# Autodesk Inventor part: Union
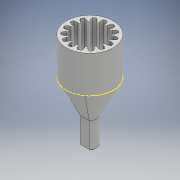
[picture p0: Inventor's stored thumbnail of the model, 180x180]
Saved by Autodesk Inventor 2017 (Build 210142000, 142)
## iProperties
Created: 2019-07
Part Number: Union
Material: Genérico
Document SubType Name: Modeling
Designer: Diego
Density: 1 g/cm^3
Appearance: Valor por defecto
Sending System: Autodesk Translation Framework v8.2.0.1029
Preprocessor: ST-DEVELOPER v18
Title: C:/Users/Diego/Downloads/9/Animalitos/Engranaje.step
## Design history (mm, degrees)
feature "Body1"
sketch "Boceto1"
  geometry: C1 r 1 at (0.304, -4.722) reference; C2 r 1 at (0.304, -4.722) reference; C3 r 7 at (0.304, -4.722); A1 r 5.95 centre (0.304, -4.722) between (1.448, 1.117) and (0.879, 1.2) reference; A2 r 5.95 centre (0.304, -4.722) between (-1.025, 1.078) and (-1.58, 0.922) reference; A3 r 5.95 centre (0.304, -4.722) between (-3.269, 0.036) and (-3.712, -0.332) reference; A4 r 5.95 centre (0.304, -4.722) between (-4.896, -1.829) and (-5.151, -2.345) reference; A5 r 5.95 centre (0.304, -4.722) between (-5.623, -4.194) and (-5.646, -4.769) reference; A6 r 5.95 centre (0.304, -4.722) between (-5.325, -6.65) and (-5.112, -7.185) reference; A7 r 5.95 centre (0.304, -4.722) between (-4.054, -8.773) and (-3.642, -9.175) reference; A8 r 5.95 centre (0.304, -4.722) between (-2.03, -10.195) and (-1.49, -10.395) reference; A9 r 5.95 centre (0.304, -4.722) between (0.398, -10.671) and (0.973, -10.634) reference; A10 r 5.95 centre (0.304, -4.722) between (2.81, -10.118) and (3.32, -9.851) reference; A11 r 5.95 centre (0.304, -4.722) between (4.788, -8.632) and (5.145, -8.181) reference; A12 r 5.95 centre (0.304, -4.722) between (5.991, -6.47) and (6.134, -5.913) reference; A13 r 5.95 centre (0.304, -4.722) between (6.211, -4.006) and (6.114, -3.439) reference; A14 r 5.95 centre (0.304, -4.722) between (5.409, -1.665) and (5.09, -1.186) reference; A15 r 5.95 centre (0.304, -4.722) between (3.724, 0.147) and (3.238, 0.454) reference; 31 further points
  constraints: 1 centre point, 1 coincident, 45 other
  dimensions: "d0" = 14 diameter of C3
extrude "Extrusión1" new body sketch "Boceto1" stored distance "d1" = 10; taper "d2" = 0 deg
sketch "Boceto2"
  geometry: C1 r 7 at (0, 0) reference; A1 r 5.95 centre (0, 0) between (3.726, 4.639) and (3.26, 4.977) reference; A2 r 5.95 centre (0, 0) between (5.291, 2.722) and (5.003, 3.221) reference; A3 r 5.95 centre (0, 0) between (5.941, 0.335) and (5.88, 0.907) reference; A4 r 5.95 centre (0, 0) between (5.563, -2.11) and (5.741, -1.563) reference; A5 r 5.95 centre (0, 0) between (4.224, -4.191) and (4.609, -3.763) reference; A6 r 5.95 centre (0, 0) between (2.154, -5.546) and (2.68, -5.312) reference; A7 r 5.95 centre (0, 0) between (-0.288, -5.943) and (0.288, -5.943) reference; A8 r 5.95 centre (0, 0) between (-2.68, -5.312) and (-2.154, -5.546) reference; A9 r 5.95 centre (0, 0) between (-4.609, -3.763) and (-4.224, -4.191) reference; A10 r 5.95 centre (0, 0) between (-5.741, -1.563) and (-5.563, -2.11) reference; A11 r 5.95 centre (0, 0) between (-5.88, 0.907) and (-5.941, 0.335) reference; A12 r 5.95 centre (0, 0) between (-5.003, 3.221) and (-5.291, 2.722) reference; A13 r 5.95 centre (0, 0) between (-3.26, 4.977) and (-3.726, 4.639) reference; A14 r 5.95 centre (0, 0) between (-0.954, 5.873) and (-1.517, 5.753) reference; A15 r 5.95 centre (0, 0) between (1.517, 5.753) and (0.954, 5.873) reference; 31 further points
  constraints: 1 horizontal alignment, 44 other
extrude "Extrusión2" cut sketch "Boceto2" distance "d3" = 1; taper "d4" = 0 deg
feature "Engrosado1" dims "d5" = 0.2, "d6" = 0.2
node "Plano de trabajo1"
sketch "Boceto3"
  geometry: L1 (-125.7, 2.5)-(-129.2, 2.5); L2 (-129.2, 2.5)-(-129.2, 3.823); L3 (-129.2, 2.5)-(-129.2, 1.177); L4 (-129.4, 3.896)-(-129.4, 2.5); L5 (-129.4, 2.5)-(-129.4, 1.104); L6 (-125.7, 2.5)-(-129.2, 2.5); L7 (-129.2, 2.5)-(-129.2, 3.823); L8 (-129.2, 2.5)-(-129.2, 1.177); L9 (-129.4, 3.896)-(-129.4, 2.5); L10 (-129.4, 2.5)-(-129.4, 1.104); L11 (-125.7, 2.5)-(-129.2, 2.5); L12 (-129.2, 2.5)-(-129.2, 3.823); L13 (-129.2, 2.5)-(-129.2, 1.177); L14 (-129.4, 3.896)-(-129.4, 2.5); L15 (-129.4, 2.5)-(-129.4, 1.104); L16 (0, 0)-(0, 2); L17 (0, 2)-(0, -1.5); L18 (0, -1.5)-(-1.323, -1.5); L19 (0, -1.5)-(1.323, -1.5); C1 r 7 at (0, 0) reference; A1 r 2 centre (-127.7, 2.5) between (-129.2, 1.177) and (-129.2, 3.823); A2 r 2.2 centre (-127.7, 2.5) between (-129.4, 1.104) and (-129.4, 3.896); A3 r 2 centre (-127.7, 2.5) between (-129.2, 1.177) and (-129.2, 3.823); A4 r 2.2 centre (-127.7, 2.5) between (-129.4, 1.104) and (-129.4, 3.896); A5 r 2 centre (-127.7, 2.5) between (-129.2, 1.177) and (-129.2, 3.823); A6 r 2.2 centre (-127.7, 2.5) between (-129.4, 1.104) and (-129.4, 3.896); A7 r 2 centre (0, 0) between (1.323, -1.5) and (-1.323, -1.5); 4 further points
  constraints: 38 end point, 18 point on circle, 7 centre point, 5 point on line, 4 coincident, 3 perpendicular, 1 horizontal, 1 vertical, 6 other
  dimensions: "d8" = 4 diameter of A1; "d9" = 3.5 distance of L1.start L1.end; "d10" = 0.2 distance between parallel lines of L2 L4; "d11" = 4 diameter of A3; "d12" = 3.5 distance of L6.start L6.end; "d13" = 0.2 distance between parallel lines of L7 L9; "d14" = 4 diameter of A5; "d15" = 3.5 distance of L11.start L11.end; "d16" = 0.2 distance between parallel lines of L12 L14; "d17" = 4 diameter of A7; "d18" = 3.5 distance of L16.end L17.end
extrude "Extrusión3" join sketch "Boceto3" distance "d19" = 8; taper "d20" = 0 deg
sketch "Boceto4"
  geometry: L1 (-1.323, -1.5)-(1.323, -1.5) reference; A1 r 2 centre (0, 0) between (1.323, -1.5) and (-1.323, -1.5) reference; 1 further point
  node "Contorno proyectado3"
sketch "Boceto5"
  geometry: C1 r 7 at (0, 0) reference; 1 further point
feature "Solevación1" dims "d21" = 0, "d22" = 90 deg, "d23" = 0, "d24" = 90 deg
  node "Aristas1"
chamfer "Chaflán1" distance "d25" = 0.5; stored, may be unused: second distance "d26" = 2, angle "d27" = 45 deg
node "Sólido1"
node "Contorno proyectado1"
node "Sólido2"
node "Contorno proyectado2"
